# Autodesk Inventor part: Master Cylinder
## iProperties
Shininess: 63.0
Angle Display Precision: 2
Document Length Units: 11269
Document Angle Units: 11279
Document Time Units: 11290
Document Mass Units: 11283
Document Length Units Precision: 3
Document Angle Units Precision: 2
Compacted: True
Created: 2001-08
Part Number: Master Cylinder
Document SubType Name: Modeling
Designer: Martin Budgell
Density: 0.0
Volumn: 0.0
Area: 0.0
PropertySet Name: Model Information
Control State: 0
Master: False
Checked Out: False
Author: Martin Budgell
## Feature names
1. Extrusion1
2. Extrusion2
3. Extrusion5
4. Fillet1
5. Fillet2
6. Fillet3
7. Fillet4
8. Fillet5
9. Chamfer1
10. Extrusion7
11. Fillet6
12. Fillet7
13. Extrusion8
14. Revolution2
15. Extrusion9
16. Fillet8
17. Extrusion10
18. Fillet9
19. Extrusion11
20. Hole1
21. Fillet10
22. Hole2
